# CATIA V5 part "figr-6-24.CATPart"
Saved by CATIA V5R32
Part number: Part1
Bounding box of the stored display mesh (mm): x -120 to 0, y 0 to 90, z -46 to 145
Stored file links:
  D:\PROJECTS\Project 2022\CATIA V5 6R 2022\Resources\Part Files\c06_catia_v5_6r2022_prt\figr-6-24.CATPart
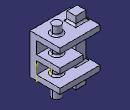
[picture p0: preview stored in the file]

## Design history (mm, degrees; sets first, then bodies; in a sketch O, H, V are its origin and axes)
Body1 (main body)
  Sketch1 on zx-plane, origin (0, 0, 0), H (-1, 0, 0), V (0, 0, 1)
    line L1 (0, 0) -> (120, 0)
    line L2 (120, 0) -> (120, 120)
    line L3 (120, 120) -> (0, 120)
    line L4 (0, 120) -> (0, 0)
    length L3 = 120
    length L2 = 120
    horizontal: L1 H, L3 H
    vertical: L2 V, L4 V
  Pad1: profile Sketch1, direction (0, 1, 0), length 20
  Sketch2 on end face of Pad1, origin (0, 20, 0), H (-1, 0, 0), V (0, 0, 1)
    projected line E1 (120, 120) -> (0, 120) from edge [face of Pad1 from Sketch1.L3 | end face of Pad1]
    point P1 (120, 120)
    line L1 (120, 120) -> (120, 104)
    line L2 (120, 104) -> (0, 104)
    line L3 (0, 104) -> (0, 120)
    point P3 (120, 120)
    length L1 = 16
    horizontal: L2 H
    vertical: L1 V, L3 V
    coincidence: P1 P3
  Sketch3 on end face of Pad1, origin (0, 20, 0), H (-1, 0, 0), V (0, 0, 1)
  Pad2: profile Sketch2, direction (0, 1, 0), length 70
  Sketch4 on end face of Pad1, origin (0, 20, 0), H (-1, 0, 0), V (0, 0, 1)
    projected line E1 (0, 0) -> (120, 0) from edge [face of Pad1 from Sketch1.L1 | end face of Pad1]
    point P1 (0, 0)
    point P3 (0, 16)
    line L1 (0, 16) -> (120, 16)
    line L2 (120, 16) -> (120, 0)
    line L3 (0, 0) -> (0, 16)
    point P5 (0, 0)
    length L2 = 16
    coincidence: P3 V, P1 P5
    horizontal: L1 H
    vertical: L2 V, L3 V
  Pad3: profile Sketch4, direction (0, 1, 0), length 70
  Sketch5 on end face of Pad1, origin (0, 20, 0), H (-1, 0, 0), V (0, 0, 1)
    point P1 (0, 68)
    line L1 (0, 68) -> (70, 68)
    line L2 (70, 68) -> (70, 52)
    line L3 (70, 52) -> (0, 52)
    line L4 (0, 52) -> (0, 68)
    coincidence: P1 V
    horizontal: L1 H, L3 H
    vertical: L2 V, L4 V
  Pad4: profile Sketch5, direction (0, 1, 0), length 70
  Sketch6 on face of Pad2, origin (0, 0, 120), H (1, 0, 0), V (0, 1, 0)
    circle A1 centre (-35, 45) radius 12.5
    radius A1 = 12.5
  Pad5: profile Sketch6, direction (0, 0, 1), length 25, opposite side length 165
  Fillet1: radius 5, on 1 edge
  Sketch7 on end face of Pad5, origin (0, 0, 145), H (1, 0, 0), V (0, 1, 0)
    line L1 (-112.0652, 55.7992) -> (-81.4586, 55.7992)
    line L2 (-81.4586, 55.7992) -> (-81.4586, 29.3395)
    line L3 (-81.4586, 29.3395) -> (-112.0652, 29.3395)
    line L4 (-112.0652, 29.3395) -> (-112.0652, 55.7992)
    horizontal: L1 H, L3 H
    vertical: L2 V, L4 V
  Pad6: profile Sketch7, direction (0, 0, -1), length 191
  Fillet2: radius 5, on 1 edge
